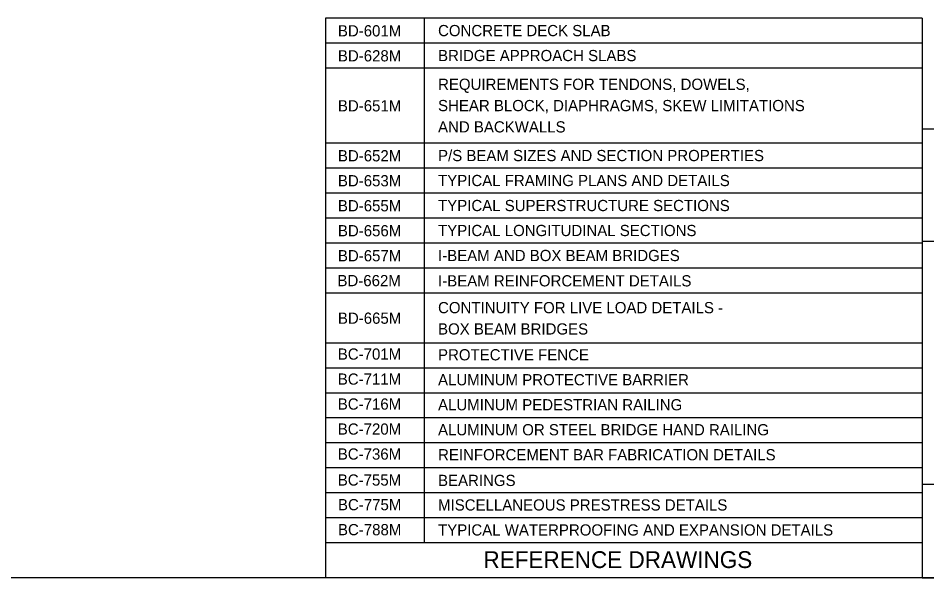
# Model space of a CAD drawing. Extents: x 639331 to 643089, y 299088 to 300975.
# Drawn here: x 639674.8 to 639917.8, y 300290.7 to 300440.4 of the extents above; entities that cross this region are included whole.
import ezdxf

# ---------------------------------------------------------------- set-up
doc = ezdxf.new("R2010")
doc.units = 0
doc.layers.add('1', color=7, linetype='Continuous')

msp = doc.modelspace()

# ---------------------------------------------------------------- linework, layer by layer
at = {"layer": '1'}
for p, q in [((639756.98, 300440.38), (639756.98, 300290.66)), ((639916.56, 300440.38), (639756.98, 300440.38)), ((639783.42, 300440.38), (639783.42, 300299.99)), ((639916.56, 300440.38), (639916.56, 300290.66)), ((639916.56, 300433.7), (639756.98, 300433.7)), ((639916.56, 300427.01), (639756.98, 300427.01)), ((640116.56, 300410.66), (639916.56, 300410.66)), ((639916.56, 300406.95), (639756.98, 300406.95)), ((639916.56, 300400.27), (639756.98, 300400.27)), ((639916.56, 300393.58), (639756.98, 300393.58)), ((639916.56, 300386.9), (639756.98, 300386.9)), ((640116.56, 300380.66), (639916.56, 300380.66)), ((639916.56, 300380.21), (639756.98, 300380.21)), ((639916.56, 300373.53), (639756.98, 300373.53)), ((639916.56, 300366.84), (639756.98, 300366.84)), ((639916.56, 300353.47), (639756.98, 300353.47)), ((639916.56, 300346.79), (639756.98, 300346.79)), ((639916.56, 300340.1), (639756.98, 300340.1)), ((639916.56, 300333.42), (639756.98, 300333.42)), ((639916.56, 300326.73), (639756.98, 300326.73)), ((639916.56, 300320.05), (639756.98, 300320.05)), ((640116.56, 300315.66), (639916.56, 300315.66)), ((639916.56, 300313.36), (639756.98, 300313.36)), ((639916.56, 300306.68), (639756.98, 300306.68)), ((639916.56, 300299.99), (639756.98, 300299.99)), ((640116.56, 300290.66), (639330.56, 300290.66)), ((639916.56, 300290.66), (640116.56, 300290.66))]:
    msp.add_line(p, q, dxfattribs=at)

# ---------------------------------------------------------------- texts
for s, p in [('BD-601M', (639760.32, 300435.5)), ('BD-628M', (639760.32, 300428.81)), ('BD-651M', (639760.32, 300415.44)), ('BD-652M', (639760.32, 300402.07)), ('BD-653M', (639760.32, 300395.39)), ('BD-655M', (639760.32, 300388.7)), ('BD-656M', (639760.32, 300382.02)), ('BD-657M', (639760.32, 300375.33)), ('BD-662M', (639760.2, 300368.67)), ('BD-665M', (639760.32, 300358.62)), ('BC-736M', (639760.29, 300322.28)), ('BC-775M', (639760.34, 300308.73)), ('BC-788M', (639760.34, 300302.05))]:
    msp.add_text(s, height=3, rotation=360, dxfattribs=at).set_placement(p)
for s, height, p in [('CONCRETE DECK SLAB', 3, (639787.1, 300435.56)), ('BRIDGE APPROACH SLABS', 3, (639787.1, 300428.88)), ('REQUIREMENTS FOR TENDONS, DOWELS,', 3, (639787.1, 300421.2)), ('SHEAR BLOCK, DIAPHRAGMS, SKEW LIMITATIONS', 3, (639787.1, 300415.5)), ('AND BACKWALLS', 3, (639787.1, 300409.8)), ('P/S BEAM SIZES AND SECTION PROPERTIES', 3, (639787.1, 300402.13)), ('TYPICAL FRAMING PLANS AND DETAILS', 3, (639787.1, 300395.45)), ('TYPICAL SUPERSTRUCTURE SECTIONS', 3, (639787.1, 300388.76)), ('TYPICAL LONGITUDINAL SECTIONS', 3, (639787.1, 300382.08)), ('I-BEAM AND BOX BEAM BRIDGES', 3, (639787.1, 300375.39)), ('I-BEAM REINFORCEMENT DETAILS', 3, (639787.1, 300368.62)), ('CONTINUITY FOR LIVE LOAD DETAILS -', 3, (639787.1, 300361.44)), ('BOX BEAM BRIDGES', 3, (639787.1, 300355.74)), ('BC-701M', 3, (639760.29, 300349.02)), ('PROTECTIVE FENCE', 3, (639787.1, 300348.83)), ('BC-711M', 3, (639760.29, 300342.33)), ('ALUMINUM PROTECTIVE BARRIER', 3, (639787.1, 300342.15)), ('BC-716M', 3, (639760.29, 300335.65)), ('ALUMINUM PEDESTRIAN RAILING', 3, (639787.1, 300335.46)), ('BC-720M', 3, (639760.29, 300328.96)), ('ALUMINUM OR STEEL BRIDGE HAND RAILING', 3, (639787.1, 300328.78)), ('REINFORCEMENT BAR FABRICATION DETAILS', 3, (639787.1, 300322.09)), ('BC-755M', 3, (639760.29, 300315.33)), ('BEARINGS', 3, (639787.1, 300315.22)), ('MISCELLANEOUS PRESTRESS DETAILS', 3, (639787.1, 300308.66)), ('TYPICAL WATERPROOFING AND EXPANSION DETAILS', 3, (639787.1, 300301.97)), ('REFERENCE DRAWINGS', 4.5, (639799.24, 300293.28))]:
    msp.add_text(s, height=height, dxfattribs=at).set_placement(p)

doc.saveas('drawing.dxf')
